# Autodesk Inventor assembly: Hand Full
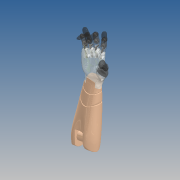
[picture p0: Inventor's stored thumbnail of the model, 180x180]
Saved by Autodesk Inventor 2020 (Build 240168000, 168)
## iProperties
Created: 2019-10
Part Number: Hand Full
Document SubType Name: Assembly
Designer: yello
Author: yello
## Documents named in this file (21)
- C:\Users\yello\Documents\Mechanical Hand\Prototype 2 (Realistic Hand)\Hand Full.iam
- C:\Users\yello\Documents\Mechanical Hand\Prototype 2 (Realistic Hand)\Palm.ipt
- C:\Users\yello\Documents\Mechanical Hand\Prototype 2 (Realistic Hand)\Wrist Rotation.ipt
- C:\Users\yello\Documents\Mechanical Hand\Prototype 2 (Realistic Hand)\Arm to Wrist Connection.ipt
- C:\Users\yello\Documents\Mechanical Hand\Prototype 2 (Realistic Hand)\Arm.ipt
- C:\Users\yello\Documents\Mechanical Hand\Prototype 2 (Realistic Hand)\Segment Thumb Finger Bottom.ipt
- C:\Users\yello\Documents\Mechanical Hand\Prototype 2 (Realistic Hand)\Segment Thumb Finger Middle.ipt
- C:\Users\yello\Documents\Mechanical Hand\Prototype 2 (Realistic Hand)\Segment Thumb Finger Top.ipt
- C:\Users\yello\Documents\Mechanical Hand\Prototype 2 (Realistic Hand)\Segment Index Finger Middle.ipt
- C:\Users\yello\Documents\Mechanical Hand\Prototype 2 (Realistic Hand)\Segment Index Finger Top.ipt
- C:\Users\yello\Documents\Mechanical Hand\Prototype 2 (Realistic Hand)\Segment Middle Finger Middle.ipt
- C:\Users\yello\Documents\Mechanical Hand\Prototype 2 (Realistic Hand)\Segment Middle Finger Top.ipt
- C:\Users\yello\Documents\Mechanical Hand\Prototype 2 (Realistic Hand)\Segment Ring Finger Middle.ipt
- C:\Users\yello\Documents\Mechanical Hand\Prototype 2 (Realistic Hand)\Segment Ring Finger Top.ipt
- C:\Users\yello\Documents\Mechanical Hand\Prototype 2 (Realistic Hand)\Segment Pinkie Finger Middle.ipt
- C:\Users\yello\Documents\Mechanical Hand\Prototype 2 (Realistic Hand)\Segment Pinkie Finger Top.ipt
- C:\Users\yello\Documents\Mechanical Hand\Prototype 2 (Realistic Hand)\Segment Index Finger Bottom Ball.iam
- C:\Users\yello\Documents\Mechanical Hand\Prototype 2 (Realistic Hand)\Segment Middle Finger Bottom Ball.iam
- C:\Users\yello\Documents\Mechanical Hand\Prototype 2 (Realistic Hand)\Segment Ring Finger Bottom Ball.iam
- C:\Users\yello\Documents\Mechanical Hand\Prototype 2 (Realistic Hand)\Segment Pinkie Finger Bottom Ball.iam
- C:\Users\yello\Documents\Mechanical Hand\Prototype 2 (Realistic Hand)\Bearings.iam
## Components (23 placed, 20 different names)
1. Palm:1 — Rotational:1, Rotational:2, Rotational:17, Rotational:18, Rotational:19, Rotational:20
2. Wrist Rotation:1 — Rotational:1, Mate:1, Mate:2, Mate:4
3. Arm to Wrist Connection:1 — Mate:1, Mate:2, Mate:3
4. Arm:1 — Mate:3, Mate:4
5. Segment Thumb Finger Bottom:1 — Rotational:2, Rotational:3
6. Segment Thumb Finger Middle:1 — Rotational:3, Rotational:4
7. Segment Thumb Finger Top:1 — Rotational:4
8. Segment Index Finger Middle:1 — Rotational:24, Rotational:25, Mate:5, Flush:1
9. Segment Index Finger Top:1 — Rotational:25
10. Segment Middle Finger Middle:1 — Rotational:10, Rotational:23, Mate:6, Flush:2
11. Segment Middle Finger Top:1 — Rotational:10
12. Segment Ring Finger Middle:1 — Rotational:13, Rotational:22, Mate:7, Flush:3
13. Segment Ring Finger Top:1 — Rotational:13
14. Segment Pinkie Finger Middle:1 — Rotational:16, Rotational:21, Mate:8, Flush:4
15. Segment Pinkie Finger Top:1 — Rotational:16
16. Segment Index Finger Bottom Ball:1 [sub-assembly] — Rotational:17, Rotational:24
17. Segment Middle Finger Bottom Ball:1 [sub-assembly] — Rotational:18, Rotational:23
18. Segment Ring Finger Bottom Ball:1 [sub-assembly] — Rotational:19, Rotational:22
19. Segment Pinkie Finger Bottom Ball:1 [sub-assembly] — Rotational:20, Rotational:21
20. Bearings:1 [sub-assembly] — Mate:5, Flush:1
21. Bearings:2 [sub-assembly] — Mate:6, Flush:2
22. Bearings:3 [sub-assembly] — Mate:7, Flush:3
23. Bearings:4 [sub-assembly] — Mate:8, Flush:4
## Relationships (28: RevoluteJoint 16, Mate 8, Flush 4)
- Rotational:1 [RevoluteJoint]: Palm:1 ↔ Wrist Rotation:1
- Mate:1: Wrist Rotation:1 ↔ Arm to Wrist Connection:1
- Mate:2: Wrist Rotation:1 ↔ Arm to Wrist Connection:1
- Mate:3: Arm to Wrist Connection:1 ↔ Arm:1
- Mate:4: Wrist Rotation:1 ↔ Arm:1
- Rotational:2 [RevoluteJoint]: Palm:1 ↔ Segment Thumb Finger Bottom:1
- Rotational:3 [RevoluteJoint]: Segment Thumb Finger Bottom:1 ↔ Segment Thumb Finger Middle:1
- Rotational:4 [RevoluteJoint]: Segment Thumb Finger Middle:1 ↔ Segment Thumb Finger Top:1
- Rotational:10 [RevoluteJoint]: Segment Middle Finger Middle:1 ↔ Segment Middle Finger Top:1
- Rotational:13 [RevoluteJoint]: Segment Ring Finger Middle:1 ↔ Segment Ring Finger Top:1
- Rotational:16 [RevoluteJoint]: Segment Pinkie Finger Middle:1 ↔ Segment Pinkie Finger Top:1
- Rotational:17 [RevoluteJoint]: Palm:1 ↔ Segment Index Finger Bottom Ball:1
- Rotational:18 [RevoluteJoint]: Palm:1 ↔ Segment Middle Finger Bottom Ball:1
- Rotational:19 [RevoluteJoint]: Palm:1 ↔ Segment Ring Finger Bottom Ball:1
- Rotational:20 [RevoluteJoint]: Palm:1 ↔ Segment Pinkie Finger Bottom Ball:1
- Rotational:21 [RevoluteJoint]: Segment Pinkie Finger Middle:1 ↔ Segment Pinkie Finger Bottom Ball:1
- Rotational:22 [RevoluteJoint]: Segment Ring Finger Middle:1 ↔ Segment Ring Finger Bottom Ball:1
- Rotational:23 [RevoluteJoint]: Segment Middle Finger Middle:1 ↔ Segment Middle Finger Bottom Ball:1
- Rotational:24 [RevoluteJoint]: Segment Index Finger Middle:1 ↔ Segment Index Finger Bottom Ball:1
- Rotational:25 [RevoluteJoint]: Segment Index Finger Middle:1 ↔ Segment Index Finger Top:1
- Mate:5: Segment Index Finger Middle:1 ↔ Bearings:1
- Flush:1: Segment Index Finger Middle:1 ↔ Bearings:1
- Mate:6: Segment Middle Finger Middle:1 ↔ Bearings:2
- Flush:2: Segment Middle Finger Middle:1 ↔ Bearings:2
- Mate:7: Segment Ring Finger Middle:1 ↔ Bearings:3
- Flush:3: Segment Ring Finger Middle:1 ↔ Bearings:3
- Mate:8: Segment Pinkie Finger Middle:1 ↔ Bearings:4
- Flush:4: Segment Pinkie Finger Middle:1 ↔ Bearings:4
